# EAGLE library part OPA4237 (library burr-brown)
Single-Supply Operational Amplifiers MicroAmplifier(TM) Series
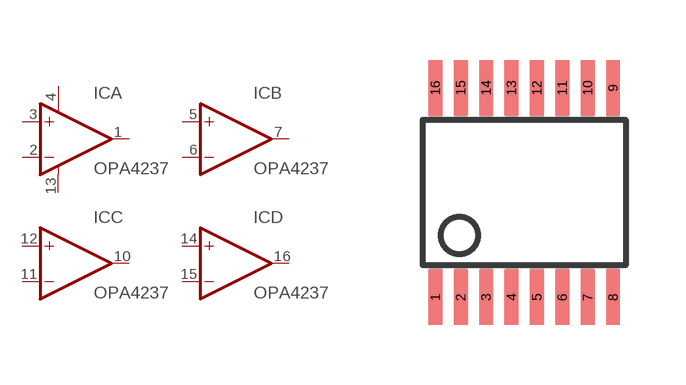
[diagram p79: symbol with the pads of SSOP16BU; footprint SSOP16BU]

Designator prefix IC; gates A=OP-AMP+- B=OP-AMP C=OP-AMP D=OP-AMP

## OPA4237U (OC_FARNELL: unknown; OC_NEWARK: unknown)  [SSOP16BU]
1  A:OUT  out
2  A:-IN  in
3  A:+IN  in
4  A:V+  pwr
5  B:+IN  in
6  B:-IN  in
7  B:OUT  out
10  C:OUT  out
11  C:-IN  in
12  C:+IN  in
13  A:V-  pwr
14  D:+IN  in
15  D:-IN  in
16  D:OUT  out

## Footprint SSOP16BU (pad centres in mm)
Small Shrink Outline Package Source: http://focus.ti.com/lit/ml/msoi004e/msoi004e.pdf
smd 0.348 x 1.397: 1 -2.223,-2.619; 2 -1.588,-2.62; 3 -0.953,-2.62; 4 -0.318,-2.62; 5 0.318,-2.62; 6 0.953,-2.62; 7 1.588,-2.62; 8 2.223,-2.62; 9 2.223,2.62; 10 1.588,2.62; 11 0.953,2.62; 12 0.318,2.62; 13 -0.318,2.62; 14 -0.953,2.62; 15 -1.588,2.62; 16 -2.223,2.62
